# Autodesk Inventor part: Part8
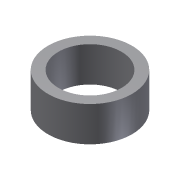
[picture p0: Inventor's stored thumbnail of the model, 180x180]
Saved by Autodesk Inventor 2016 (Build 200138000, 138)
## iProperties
Shininess: 77.0
Length Units: 11269
Angle Units: 11279
Time Units: 11290
Mass Units: 11283
Length Display Precision: 3
Angle Display Precision: 2
Created: 2002-01
Part Number: Part8
Document SubType Name: Modeling
Designer: ***
Density: 1 g/cm^3
Material: Generic
Appearance: Default
Density: 0.0
Volumn: 0.0
Area: 0.0
PropertySet Name: Model Information
Control State: 0
Master: False
Checked Out: False
Author: ***
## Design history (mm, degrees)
sketch "Sketch1"
  geometry: C1 r 30 at (0, 0); C2 r 22.5 at (0, 0)
  constraints: 2 centre point, 1 coincident
  dimensions: "d0" = 60 diameter of C1; "d1" = 45 diameter of C2
extrude "Extrusion1" new body sketch "Sketch1" distance "d2" = 25; taper "d3" = 0 deg
body "Solid1"
